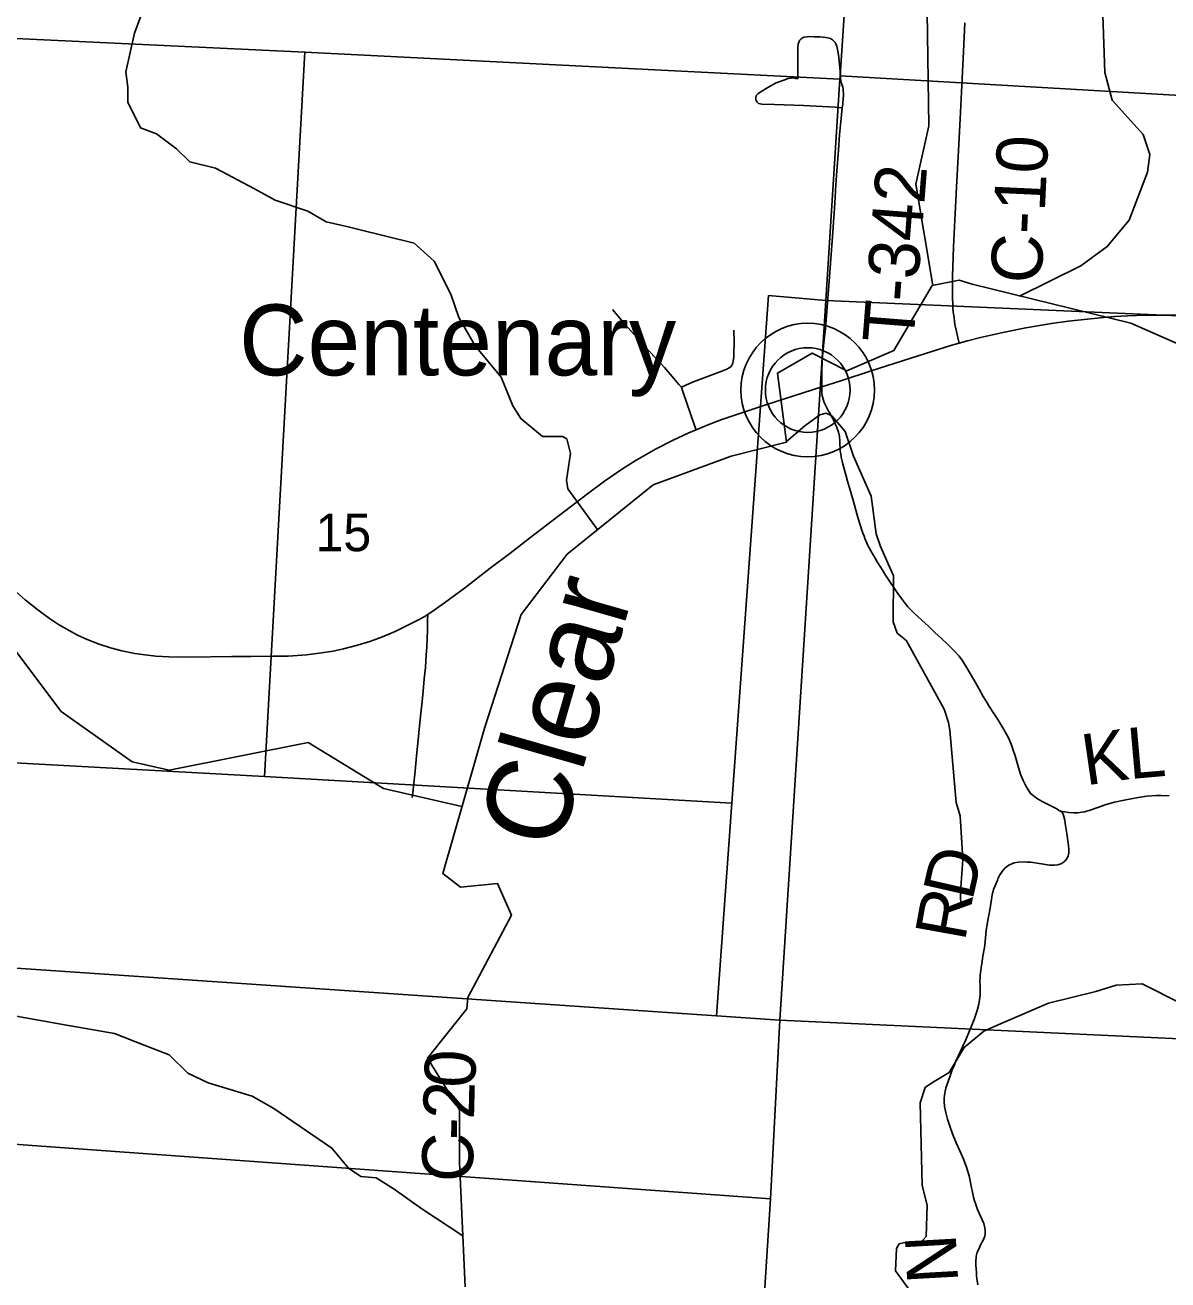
# Model space of a CAD drawing. Extents: x 0 to 34, y 0 to 22.
# Drawn here: x 3.179 to 4.453, y 17.749 to 19.148 of the extents above; entities that cross this region are included whole.
import ezdxf

# ---------------------------------------------------------------- set-up
doc = ezdxf.new("R2010")
doc.units = 0
for name, color, linetype in [('GM_X_County_Road', 7, 'Continuous'), ('GM_X_County_Road_Text', 7, 'Continuous'), ('GM_X_Minor_River', 7, 'Continuous'), ('GM_X_Minor_River_Text', 7, 'Continuous'), ('GM_X_Section', 7, 'Continuous'), ('GM_X_Section_Text', 7, 'Continuous'), ('GM_X_State_Route', 7, 'Continuous'), ('GM_X_Township_Road', 7, 'Continuous'), ('GM_X_Township_Road_Text', 7, 'Continuous'), ('GM_X_Unincorporated', 7, 'Continuous'), ('GM_X_Unincorporated_Location', 7, 'Continuous'), ('GM_X_Unincorporated_Text', 7, 'Continuous')]:
    doc.layers.add(name, color=color, linetype=linetype)

msp = doc.modelspace()

# ---------------------------------------------------------------- linework, layer by layer
at = {"layer": 'GM_X_County_Road'}
for points in [[(4.2201, 18.7932), (4.2185, 18.7992), (4.217, 18.806), (4.2155, 18.814), (4.2144, 18.8212), (4.2136, 18.8279), (4.2132, 18.8327), (4.213, 18.8372), (4.2128, 18.8423), (4.2128, 18.8688), (4.213, 18.8775), (4.214, 18.9004), (4.2147, 18.9153), (4.2158, 18.9377), (4.2173, 18.9668), (4.2194, 19.0078), (4.2213, 19.0432), (4.2228, 19.0729), (4.2248, 19.1182), (4.2263, 19.1499)], [(3.6104, 18.2869), (3.611, 18.2919), (3.6136, 18.3166), (3.6157, 18.337), (3.6171, 18.3509), (3.6187, 18.3666), (3.6202, 18.3808), (3.6215, 18.3939), (3.6226, 18.4054), (3.6239, 18.419), (3.6251, 18.4316), (3.6261, 18.4456), (3.6268, 18.4539), (3.6276, 18.4732), (3.6276, 18.4852), (3.6277, 18.4908)]]:
    msp.add_lwpolyline(points, dxfattribs=at)
at = {"layer": 'GM_X_Minor_River'}
for points in [[(4.1907, 18.8574), (4.1719, 18.9702), (4.1862, 19.0352), (4.1845, 19.1623), (4.1415, 19.2276), (4.075, 19.2911), (4.0757, 19.3594), (4.0541, 19.4097), (4.057, 19.5938), (4.0546, 19.6579), (4.0103, 19.7941), (3.9887, 19.9981), (3.9324, 20.1513), (3.8898, 20.2086), (3.6983, 20.2805), (3.6841, 20.2933), (3.6464, 20.3317), (3.5061, 20.3456), (3.3197, 20.2301), (3.2986, 20.2204)], [(3.8165, 18.5859), (3.7839, 18.6309), (3.7824, 18.6404), (3.7869, 18.67), (3.7828, 18.6864), (3.7778, 18.689), (3.7555, 18.689), (3.7316, 18.7091), (3.7225, 18.7232), (3.7096, 18.7551), (3.6805, 18.7901), (3.6623, 18.8216), (3.6536, 18.8478), (3.635, 18.8843), (3.6126, 18.9044), (3.5494, 18.9203), (3.5391, 18.9226), (3.5145, 18.9283), (3.494, 18.94), (3.4576, 18.9525), (3.4345, 18.965), (3.3913, 18.9882), (3.3625, 18.995), (3.3477, 19.0098), (3.3254, 19.0265), (3.3075, 19.0329), (3.2935, 19.0618), (3.2935, 19.0782), (3.2913, 19.0953), (3.3008, 19.1386), (3.3167, 19.182)], [(4.2875, 18.8455), (4.3556, 18.8794), (4.3852, 18.9007), (4.4095, 18.93), (4.43, 18.9836), (4.4326, 19.0034), (4.4254, 19.0258), (4.3906, 19.0638), (4.3826, 19.0946), (4.3804, 19.1588)], [(3.6695, 17.7413), (3.6631, 17.8798), (3.6631, 17.9386), (3.6274, 17.9963), (3.6715, 18.0514), (3.6724, 18.0639), (3.721, 18.1555), (3.7057, 18.191), (3.6644, 18.1868), (3.6444, 18.2022), (3.6913, 18.3651), (3.7318, 18.4907), (3.7833, 18.558), (3.8791, 18.6351), (3.9659, 18.667), (4.0276, 18.6827), (4.0175, 18.7597), (4.0563, 18.782), (4.0949, 18.7623), (4.1474, 18.7848), (4.1901, 18.8573), (4.22, 18.8632), (4.2345, 18.8588), (4.4116, 18.8152), (4.5005, 18.7762)], [(4.0275, 18.6835), (4.0481, 18.7011), (4.0648, 18.7133), (4.072, 18.7152), (4.0781, 18.7122), (4.0929, 18.6947), (4.1023, 18.667), (4.122, 18.6225), (4.1277, 18.5807), (4.1326, 18.5663), (4.147, 18.5336), (4.1466, 18.4826), (4.1512, 18.4697), (4.1561, 18.4659), (4.1614, 18.4613), (4.2034, 18.385), (4.2084, 18.3705), (4.2099, 18.3618), (4.2167, 18.2812), (4.2212, 18.2664), (4.2242, 18.2177), (4.2216, 18.1812), (4.2219, 18.1637)], [(3.6658, 18.2766), (3.5783, 18.2969), (3.4945, 18.3481), (3.3396, 18.3171), (3.2981, 18.3263), (3.2192, 18.3825), (3.1427, 18.4839)], [(4.1759, 17.7226), (4.149, 17.7591), (4.1502, 17.7842), (4.1532, 17.7895), (4.1596, 17.7907), (4.1767, 17.7899), (4.1835, 17.7975), (4.1843, 17.8325), (4.179, 17.8542), (4.1767, 17.9466), (4.1824, 17.9637), (4.1904, 17.969), (4.209, 17.9804), (4.2257, 18.0082), (4.2477, 18.0265), (4.2697, 18.036), (4.3197, 18.0577), (4.3724, 18.0707), (4.3951, 18.0776), (4.4243, 18.0791), (4.4675, 18.0571), (4.5032, 18.0446)], [(3.6669, 17.7983), (3.621, 17.8285), (3.5903, 17.8501), (3.5702, 17.8627), (3.5531, 17.8645), (3.5395, 17.8737), (3.5209, 17.8961), (3.4561, 17.9401), (3.4322, 17.9538), (3.383, 17.9689), (3.3602, 17.9795), (3.3394, 18), (3.3117, 18.0107), (3.2787, 18.0239), (3.2295, 18.0322), (3.2249, 18.033), (3.1544, 18.0455), (3.1233, 18.0409), (3.0854, 18.0446), (3.0703, 18.0457), (3.0396, 18.0396), (3.0073, 18.0415), (2.9687, 18.0434), (2.941, 18.0384)]]:
    msp.add_lwpolyline(points, dxfattribs=at)
at = {"layer": 'GM_X_Section'}
for points in [[(3.1221, 20.1708), (4.1536, 20.1097), (4.1266, 19.6923), (4.0998, 19.2759), (4.0875, 19.0909), (4.0872, 19.0874), (3.4908, 19.1174), (3.0501, 19.1382), (3.0637, 19.3317), (3.093, 19.7459)], [(4.0998, 19.2759), (5.159, 19.2125), (5.1485, 19.0298), (4.0875, 19.0909)], [(3.0501, 19.1382), (3.4908, 19.1174), (3.4459, 18.3102), (2.9978, 18.3347), (3.0349, 18.9043)], [(3.4908, 19.1174), (4.0872, 19.0874), (4.0716, 18.8408), (4.0077, 18.8461), (3.9669, 18.2803), (3.4459, 18.3102)], [(4.0872, 19.0874), (4.0875, 19.0909), (5.1485, 19.0298), (5.1344, 18.7947), (4.5508, 18.82), (4.0716, 18.8408)], [(4.0716, 18.8408), (4.0202, 18.0387), (3.9498, 18.0434), (3.9669, 18.2803), (4.0077, 18.8461)], [(4.5508, 18.82), (4.4977, 18.0162), (4.0202, 18.0387), (4.0716, 18.8408)], [(3.4459, 18.3102), (3.9669, 18.2803), (3.9498, 18.0434), (2.9831, 18.1092), (2.9978, 18.3347)], [(2.9831, 18.1092), (3.9498, 18.0434), (4.0202, 18.0387), (4.01, 17.8394), (2.9705, 17.9146)], [(4.0202, 18.0387), (4.4977, 18.0162), (5.0782, 18.0036), (5.0081, 16.9831), (4.4681, 17.0085), (3.9555, 17.0086), (3.9833, 17.4262), (4.01, 17.8394)], [(4.01, 17.8394), (3.9833, 17.4262), (2.9438, 17.505), (2.9705, 17.9146)]]:
    msp.add_lwpolyline(points, close=True, dxfattribs=at)
at = {"layer": 'GM_X_State_Route'}
for points in [[(3.6086, 18.4802), (3.6166, 18.4843), (3.6236, 18.4881), (3.6277, 18.4908), (3.6351, 18.4956), (3.6464, 18.5035), (3.6689, 18.5202), (3.6974, 18.5422), (3.7192, 18.5587), (3.7412, 18.5759), (3.8059, 18.6252), (3.8249, 18.6392), (3.8447, 18.6531), (3.859, 18.6619), (3.8816, 18.6748), (3.9015, 18.6849), (3.9189, 18.6931), (3.9271, 18.6965), (3.9412, 18.7026), (3.9557, 18.7081), (4.0046, 18.7244), (4.0669, 18.7443), (4.0884, 18.7511), (4.1222, 18.7624), (4.1661, 18.7762), (4.2118, 18.7908), (4.2201, 18.7932), (4.2293, 18.7956), (4.2439, 18.7994), (4.2706, 18.8054), (4.2943, 18.8102), (4.3231, 18.815), (4.3416, 18.8175), (4.3811, 18.8217), (4.3938, 18.8227), (4.4077, 18.8234), (4.4282, 18.8242), (4.4797, 18.8244)], [(3.1693, 18.5156), (3.1791, 18.5071), (3.1932, 18.4958), (3.2063, 18.4862), (3.2162, 18.4797), (3.228, 18.4727), (3.2374, 18.4678), (3.2482, 18.4629), (3.2615, 18.4577), (3.274, 18.4536), (3.2867, 18.4503), (3.3013, 18.4473), (3.3124, 18.4456), (3.3248, 18.4442), (3.3391, 18.4435), (3.3621, 18.4433), (3.4093, 18.444), (3.4304, 18.444), (3.4547, 18.4441), (3.4721, 18.4444), (3.4926, 18.4459), (3.5068, 18.4475), (3.5222, 18.4499), (3.5338, 18.4524), (3.5495, 18.4565), (3.5632, 18.4606), (3.5772, 18.4658), (3.5915, 18.4718), (3.6033, 18.4775), (3.6086, 18.4802)]]:
    msp.add_lwpolyline(points, dxfattribs=at)
at = {"layer": 'GM_X_Township_Road'}
for points in [[(4.0899, 19.0554), (4.0903, 19.0596), (4.091, 19.0662), (4.0912, 19.0686), (4.0912, 19.0714), (4.091, 19.0742), (4.0907, 19.0766), (4.0904, 19.0783), (4.0898, 19.0805), (4.0893, 19.0818), (4.0888, 19.0835), (4.0884, 19.0853), (4.0879, 19.089), (4.0877, 19.0914), (4.087, 19.1001), (4.0864, 19.1077), (4.0856, 19.1143), (4.0849, 19.1186), (4.0843, 19.1223), (4.0838, 19.124), (4.0828, 19.1268), (4.0821, 19.1282), (4.0798, 19.1305), (4.079, 19.1313), (4.0777, 19.1319), (4.0766, 19.1325), (4.0753, 19.1329), (4.0737, 19.1334), (4.0716, 19.1337), (4.0647, 19.1343), (4.0616, 19.1343), (4.0586, 19.1344), (4.0526, 19.1347), (4.0506, 19.1346), (4.0475, 19.1341), (4.0461, 19.1337), (4.0439, 19.1323), (4.0426, 19.1309), (4.0413, 19.1287), (4.0407, 19.1262), (4.0404, 19.1226), (4.0403, 19.1189), (4.0402, 19.1128), (4.0402, 19.0954), (4.0404, 19.0916), (4.0407, 19.0894), (4.0406, 19.0888), (4.0402, 19.0881), (4.039, 19.088), (4.0381, 19.0882), (4.036, 19.0886), (4.0348, 19.0887), (4.0337, 19.0886), (4.0326, 19.0884), (4.0297, 19.0879), (4.0246, 19.0862), (4.0162, 19.0831), (4.0067, 19.0779), (3.9984, 19.0728), (3.9959, 19.0708), (3.994, 19.069), (3.9934, 19.0664), (3.9935, 19.0644), (3.9943, 19.0626), (3.995, 19.0615), (3.9966, 19.0602), (4.0003, 19.0596), (4.0142, 19.059), (4.0466, 19.0578), (4.0819, 19.056), (4.0899, 19.0554)], [(4.0804, 18.9336), (4.0807, 18.9376), (4.0814, 18.9493), (4.0828, 18.9697), (4.0839, 18.9851), (4.0857, 19.008), (4.0869, 19.0253), (4.0891, 19.0474), (4.0899, 19.0554)], [(4.0669, 18.7443), (4.0669, 18.7521), (4.067, 18.7621), (4.0674, 18.772), (4.0682, 18.7832), (4.0701, 18.8002), (4.071, 18.8095), (4.0726, 18.8287), (4.0754, 18.862), (4.0793, 18.9168), (4.0804, 18.9336)], [(3.9271, 18.6965), (3.9253, 18.7014), (3.9121, 18.7392), (3.9106, 18.744), (3.9077, 18.7471), (3.9021, 18.7536), (3.8915, 18.7659), (3.8702, 18.7891), (3.8477, 18.814), (3.8337, 18.8307)], [(3.9106, 18.744), (3.9156, 18.7464), (3.9228, 18.7495), (3.9289, 18.7519), (3.9556, 18.7618), (3.9612, 18.7641), (3.9637, 18.7655), (3.9655, 18.7668), (3.9669, 18.7686), (3.9678, 18.7706), (3.9684, 18.7735), (3.9688, 18.7773), (3.9689, 18.7809), (3.9692, 18.7942), (3.9689, 18.8074)], [(4.2005, 18.4639), (4.1931, 18.4708), (4.1859, 18.4776), (4.1827, 18.4805), (4.1699, 18.4922), (4.1659, 18.4961), (4.163, 18.4993), (4.1603, 18.5026), (4.1559, 18.5086), (4.1519, 18.5142), (4.1467, 18.5218), (4.1431, 18.5269), (4.138, 18.5347), (4.1354, 18.5389), (4.1288, 18.5495), (4.1269, 18.5527), (4.1215, 18.5617), (4.1197, 18.5651), (4.118, 18.5682), (4.1163, 18.5722), (4.1151, 18.5752), (4.1141, 18.5779), (4.1128, 18.5814), (4.1092, 18.5927), (4.1061, 18.6027), (4.1022, 18.6165), (4.099, 18.628), (4.0958, 18.6394), (4.0938, 18.6464), (4.0904, 18.6583), (4.0897, 18.6614), (4.0886, 18.6661), (4.0881, 18.6697), (4.0876, 18.6728), (4.0871, 18.684), (4.0867, 18.689), (4.0857, 18.6939), (4.0839, 18.6992), (4.0824, 18.7025), (4.0808, 18.7061), (4.0785, 18.7104), (4.0761, 18.7149), (4.0741, 18.7182), (4.0718, 18.7225), (4.0698, 18.727), (4.0685, 18.7308), (4.0674, 18.7347), (4.0671, 18.7373), (4.0669, 18.7398), (4.0669, 18.7443)], [(4.3331, 18.2714), (4.3309, 18.2728), (4.3289, 18.2741), (4.3126, 18.2823), (4.3065, 18.286), (4.3026, 18.2888), (4.3001, 18.291), (4.297, 18.2951), (4.2943, 18.2997), (4.2914, 18.3058), (4.2889, 18.3118), (4.2863, 18.32), (4.2824, 18.3333), (4.2805, 18.3395), (4.2781, 18.3463), (4.2751, 18.3532), (4.27, 18.3625), (4.2631, 18.3736), (4.2589, 18.3802), (4.2541, 18.3877), (4.2502, 18.394), (4.2469, 18.3994), (4.2419, 18.4082), (4.2372, 18.4167), (4.2288, 18.4312), (4.2234, 18.4397), (4.2197, 18.4447), (4.2151, 18.4498), (4.2067, 18.4581), (4.2005, 18.4639)], [(4.3331, 18.2714), (4.3377, 18.2707), (4.3423, 18.2699), (4.3476, 18.2696), (4.3522, 18.2698), (4.3568, 18.2704), (4.3603, 18.2709), (4.3621, 18.2714), (4.365, 18.2721), (4.3746, 18.2756), (4.3839, 18.2789), (4.3933, 18.2817), (4.4042, 18.2839), (4.4139, 18.2858), (4.4218, 18.2871), (4.4292, 18.2881), (4.4403, 18.2889), (4.4452, 18.2889), (4.4544, 18.2886)], [(4.2408, 17.7437), (4.2399, 17.7506), (4.2396, 17.7536), (4.2393, 17.7573), (4.2388, 17.7654), (4.2387, 17.7697), (4.2392, 17.7752), (4.2403, 17.7799), (4.2423, 17.7843), (4.244, 17.7881), (4.2467, 17.7925), (4.2479, 17.7959), (4.2487, 17.7978), (4.2491, 17.8005), (4.2493, 17.8022), (4.2491, 17.8047), (4.2489, 17.8073), (4.2475, 17.8121), (4.2459, 17.8162), (4.2407, 17.8275), (4.2393, 17.8311), (4.2382, 17.8344), (4.2373, 17.8374), (4.2363, 17.8415), (4.2359, 17.8433), (4.235, 17.8469), (4.2346, 17.8487), (4.2339, 17.8517), (4.2327, 17.8578), (4.2312, 17.8651), (4.2296, 17.8711), (4.2281, 17.8759), (4.2265, 17.8797), (4.2253, 17.8828), (4.2209, 17.8928), (4.2168, 17.9019), (4.2127, 17.912), (4.2099, 17.9203), (4.2072, 17.9281), (4.2052, 17.9357), (4.2045, 17.9389), (4.2039, 17.9424), (4.2035, 17.9478), (4.2034, 17.9509), (4.2037, 17.9551), (4.2044, 17.9593), (4.2054, 17.9628), (4.2064, 17.9663), (4.2078, 17.9704), (4.2092, 17.9744), (4.2125, 17.9831), (4.2145, 17.9882), (4.2164, 17.9928), (4.2244, 18.0096), (4.2272, 18.0158), (4.2311, 18.0249), (4.2369, 18.0392), (4.2403, 18.0492), (4.2421, 18.0563), (4.2433, 18.0637), (4.2435, 18.0665), (4.2437, 18.0698), (4.2436, 18.0734), (4.2434, 18.0767), (4.2432, 18.0822), (4.2435, 18.0862), (4.2437, 18.089), (4.244, 18.0914), (4.2444, 18.0945), (4.2446, 18.0963), (4.2448, 18.0978), (4.2451, 18.0994), (4.2457, 18.1035), (4.2463, 18.1076), (4.247, 18.1117), (4.2476, 18.1157), (4.2483, 18.1195), (4.2488, 18.1222), (4.2492, 18.1263), (4.2502, 18.1384), (4.2509, 18.1432), (4.2523, 18.152), (4.2542, 18.1612), (4.2567, 18.1756), (4.2571, 18.1786), (4.258, 18.1823), (4.2586, 18.1842), (4.2595, 18.1868), (4.2609, 18.1902), (4.2628, 18.1946), (4.2634, 18.1962), (4.2656, 18.2006), (4.2672, 18.2032), (4.2687, 18.2052), (4.2716, 18.2083), (4.2754, 18.2113), (4.2787, 18.2129), (4.2815, 18.2139), (4.2863, 18.2147), (4.2925, 18.215), (4.2961, 18.2147), (4.2999, 18.2145), (4.314, 18.2123), (4.3208, 18.2114), (4.3265, 18.2112), (4.3303, 18.2118), (4.3333, 18.2128), (4.3361, 18.2143), (4.3381, 18.2159), (4.3401, 18.2184), (4.3417, 18.2219), (4.3424, 18.225), (4.3425, 18.2288), (4.3421, 18.2332), (4.34, 18.2465), (4.3383, 18.2577), (4.3378, 18.2615), (4.337, 18.2657), (4.3362, 18.268), (4.3348, 18.2699), (4.3331, 18.2714)]]:
    msp.add_lwpolyline(points, dxfattribs=at)
at = {"layer": 'GM_X_Unincorporated'}
for radius in [0.0744, 0.0472]:
    msp.add_circle((4.0513, 18.7408), radius, dxfattribs=at)
at = {"layer": 'GM_X_Unincorporated_Location'}
msp.add_line((4.0513, 18.7408), (4.0513, 18.7408), dxfattribs=at)

# ---------------------------------------------------------------- texts
at = {"layer": 'GM_X_County_Road_Text'}
for s, height, rotation, p in [('C-10', 0.05682, 87.3274, (4.3119, 18.8588)), ('0', 0.0568, 87.418, (3.6802, 17.9623)), ('2', 0.0568, 88.5636, (3.6793, 17.9276)), ('-', 0.0568, 88.7743, (3.6788, 17.9044)), ('C', 0.0568, 88.8251, (3.6778, 17.8577))]:
    msp.add_text(s, height=height, rotation=rotation, dxfattribs=at).set_placement(p)
at = {"layer": 'GM_X_Minor_River_Text'}
msp.add_text('Clear', height=0.09469, rotation=73.9989, dxfattribs=at).set_placement((3.7741, 18.2252))
at = {"layer": 'GM_X_Section_Text'}
msp.add_text('15', height=0.04186, rotation=0, dxfattribs=at).set_placement((3.5025, 18.5612))
at = {"layer": 'GM_X_Township_Road_Text'}
for s, height, rotation, p in [('T-342', 0.05682, 85.5174, (4.169, 18.7917)), ('K', 0.0568, 8.2537, (4.3613, 18.3001)), ('L', 0.0568, 5.0509, (4.41, 18.3072)), ('D', 0.0568, 77.1353, (4.2347, 18.1705)), ('R', 0.0568, 79.7311, (4.2265, 18.1253)), ('N', 0.0568, 93.1707, (4.2192, 17.7466))]:
    msp.add_text(s, height=height, rotation=rotation, dxfattribs=at).set_placement(p)
at = {"layer": 'GM_X_Unincorporated_Text'}
msp.add_text('Centenary', height=0.07898, rotation=0, dxfattribs=at).set_placement((3.4175, 18.7572))

doc.saveas('drawing.dxf')
